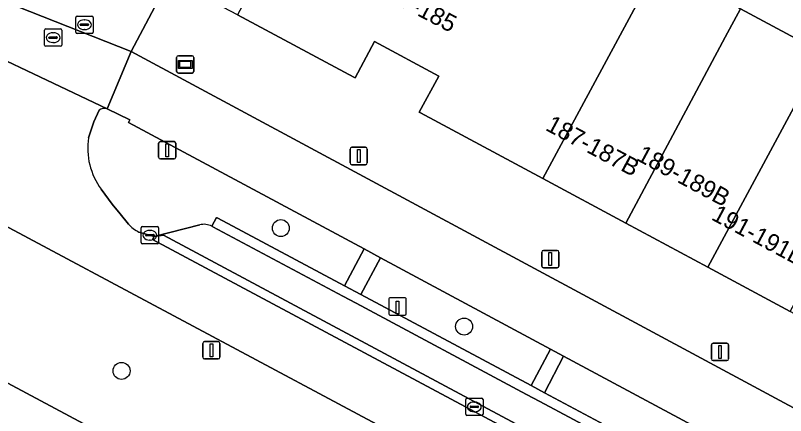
# Model space of a CAD drawing. Extents: x 159489 to 160304, y 383825 to 384531.
# Drawn here: x 159724.49 to 159768.87, y 384033.3 to 384056.37 of the extents above; entities that cross this region are included whole.
import ezdxf

# ---------------------------------------------------------------- set-up
doc = ezdxf.new("R2010")
doc.units = 0
for name, color, linetype in [('IMGEO_Berm_groen', 7, 'Continuous'), ('IMGEO_Boom', 7, 'Continuous'), ('IMGEO_Erf', 7, 'Continuous'), ('IMGEO_Fietspad_gesloten', 7, 'Continuous'), ('IMGEO_Informatiebord', 7, 'Continuous'), ('IMGEO_Kolk', 7, 'Continuous'), ('IMGEO_Laadpaal', 7, 'Continuous'), ('IMGEO_Lichtmast', 7, 'Continuous'), ('IMGEO_OVBaan_gesloten', 7, 'Continuous'), ('IMGEO_Pand', 7, 'Continuous'), ('IMGEO_Pand_nummerreeks', 7, 'Continuous'), ('IMGEO_Parkeervlak_open', 7, 'Continuous'), ('IMGEO_Rijbaan_lokaal_gesloten', 7, 'Continuous'), ('IMGEO_Rijbaan_lokaal_open', 7, 'Continuous'), ('IMGEO_Rioolput', 7, 'Continuous'), ('IMGEO_Verkeersbordpaal', 7, 'Continuous'), ('IMGEO_Voetpad_open', 7, 'Continuous')]:
    doc.layers.add(name, color=color, linetype=linetype)

msp = doc.modelspace()

# ---------------------------------------------------------------- linework, layer by layer
at = {"layer": 'IMGEO_Berm_groen'}
for points in [[(159694.802, 384052.841), (159693.976, 384051.25), (159777.482, 384006.579), (159777.79, 384007.155)], [(159729.317, 384050.915), (159729.003, 384050.242), (159728.705, 384049.324)], [(159731.013, 384050.208), (159731.079, 384050.354), (159729.77, 384050.977)], [(159735.803, 384044.218), (159736.071, 384044.724), (159736.097, 384044.71), (159736.122, 384044.696), (159736.147, 384044.681), (159743.451, 384040.779), (159744.588, 384042.906), (159731.013, 384050.208)], [(159729.441, 384046.354), (159730.06, 384045.499), (159730.518, 384044.924), (159731.001, 384044.339)], [(159794.454, 384006.529), (159791.668, 384008.018), (159791.261, 384007.258), (159782.348, 384012.022), (159782.754, 384012.782), (159722.71, 384044.871)], [(159731.607, 384043.881), (159732.479, 384043.633), (159735.114, 384044.297)]]:
    msp.add_lwpolyline(points, dxfattribs=at)
for points in [[(159745.526, 384042.402), (159744.388, 384040.278), (159754.215, 384035.027), (159755.319, 384037.135)], [(159756.08, 384036.725), (159754.979, 384034.619), (159764.491, 384029.537), (159765.597, 384031.607)]]:
    msp.add_lwpolyline(points, close=True, dxfattribs=at)
for centre, radius, start, end in [((159729.606, 384050.492), 0.513, 71.303, 124.2838), ((159732.611, 384048.716), 3.954, 171.1517, 216.6847), ((159732.536, 384045.74), 2.078, 222.3887, 243.4491), ((159735.358, 384043.377), 0.951, 62.0804, 104.8377)]:
    msp.add_arc(centre, radius, start, end, dxfattribs=at)
at = {"layer": 'IMGEO_Boom'}
for centre in [(159739.784, 384044.112), (159750.343, 384038.433), (159730.609, 384035.874)]:
    msp.add_circle(centre, 0.489, dxfattribs=at)
at = {"layer": 'IMGEO_Erf'}
msp.add_lwpolyline([(159771.882, 384093.775), (159768.398, 384087.297), (159767.715, 384087.664), (159765.263, 384083.106), (159764.285, 384083.651), (159761.719, 384078.881), (159759.162, 384074.125), (159756.604, 384069.369), (159754.192, 384064.841), (159755.61, 384064.079), (159754.307, 384061.657), (159761.088, 384058.01), (159761.728, 384059.201), (159766.267, 384056.759), (159771.029, 384054.198)], dxfattribs=at)
at = {"layer": 'IMGEO_Fietspad_gesloten'}
for points in [[(159722.803, 384054.291), (159729.77, 384050.977), (159731.166, 384054.292), (159724.587, 384056.893)], [(159731.166, 384054.292), (159729.77, 384050.977), (159731.079, 384050.354), (159731.013, 384050.208), (159744.588, 384042.906), (159745.526, 384042.402), (159755.319, 384037.135), (159756.08, 384036.725), (159765.597, 384031.607), (159765.779, 384031.509), (159766.543, 384031.098), (159776.103, 384025.957), (159776.158, 384025.928), (159776.288, 384025.857), (159777.06, 384025.441), (159789.993, 384018.658), (159793.68, 384016.677), (159793.765, 384016.631), (159793.788, 384016.619), (159793.901, 384016.538), (159794.526, 384016.198), (159800.871, 384012.75), (159801.63, 384012.412), (159802.497, 384011.87)], [(159802.594, 384011.19), (159802.971, 384011.597), (159804.049, 384012.761), (159805.225, 384014.454), (159801.988, 384016.22), (159797.098, 384018.803), (159731.166, 384054.292)]]:
    msp.add_lwpolyline(points, dxfattribs=at)
at = {"layer": 'IMGEO_Informatiebord'}
for p, q in [((159733.781, 384053.148), (159733.781, 384053.948)), ((159733.781, 384053.948), (159733.781, 384053.148)), ((159733.881, 384054.048), (159734.671, 384054.048)), ((159734.671, 384054.048), (159733.881, 384054.048)), ((159734.771, 384053.948), (159734.771, 384053.148)), ((159734.771, 384053.148), (159734.771, 384053.948)), ((159734.671, 384053.048), (159733.881, 384053.048)), ((159733.881, 384053.048), (159734.671, 384053.048))]:
    msp.add_line(p, q, dxfattribs=at)
for points in [[(159733.882, 384053.78), (159734.67, 384053.78), (159734.67, 384053.316), (159733.882, 384053.316), (159733.882, 384053.78)], [(159733.947, 384053.715), (159733.947, 384053.381), (159734.605, 384053.381), (159734.605, 384053.715), (159733.947, 384053.715)]]:
    msp.add_lwpolyline(points, dxfattribs=at)
for centre, start, end in [((159733.881, 384053.948), 90, 180), ((159733.881, 384053.948), 90, 180), ((159734.671, 384053.948), 0, 90), ((159734.671, 384053.948), 360, 90), ((159733.881, 384053.148), 180, 270), ((159733.881, 384053.148), 180, 270), ((159734.671, 384053.148), 270, 0), ((159734.671, 384053.148), 270, 0)]:
    msp.add_arc(centre, 0.1, start, end, dxfattribs=at)
at = {"layer": 'IMGEO_Kolk'}
for p, q in [((159731.739, 384043.272), (159731.739, 384044.124)), ((159731.814, 384044.198), (159732.666, 384044.198)), ((159732.74, 384044.124), (159732.74, 384043.272)), ((159731.998, 384043.692), (159731.998, 384043.704)), ((159732.041, 384043.741), (159732.439, 384043.741)), ((159732.227, 384043.978), (159732.252, 384043.978)), ((159732.482, 384043.704), (159732.482, 384043.692)), ((159732.436, 384043.655), (159732.038, 384043.655)), ((159732.25, 384043.418), (159732.225, 384043.418)), ((159732.666, 384043.198), (159731.814, 384043.198)), ((159750.435, 384033.378), (159750.435, 384034.23)), ((159750.51, 384034.304), (159751.362, 384034.304)), ((159750.923, 384034.084), (159750.948, 384034.084)), ((159751.436, 384034.23), (159751.436, 384033.378)), ((159750.694, 384033.798), (159750.694, 384033.81)), ((159751.132, 384033.761), (159750.734, 384033.761)), ((159750.737, 384033.847), (159751.135, 384033.847)), ((159750.946, 384033.524), (159750.921, 384033.524)), ((159751.178, 384033.81), (159751.178, 384033.798)), ((159751.362, 384033.304), (159750.51, 384033.304))]:
    msp.add_line(p, q, dxfattribs=at)
for points in [[(159731.739, 384043.272), (159731.739, 384044.124)], [(159731.814, 384044.198), (159732.666, 384044.198)], [(159732.74, 384044.124), (159732.74, 384043.272)], [(159732.666, 384043.198), (159731.814, 384043.198)], [(159750.435, 384033.378), (159750.435, 384034.23)], [(159750.51, 384034.304), (159751.362, 384034.304)], [(159751.436, 384034.23), (159751.436, 384033.378)], [(159751.362, 384033.304), (159750.51, 384033.304)]]:
    msp.add_lwpolyline(points, dxfattribs=at)
for centre, radius, start, end in [((159731.816, 384044.122), 0.0765, 91.552, 178.448), ((159731.816, 384044.122), 0.0765, 91.552, 178.448), ((159732.664, 384044.122), 0.0765, 1.552, 88.448), ((159732.664, 384044.122), 0.0765, 1.552, 88.448), ((159732.038, 384043.701), 0.0403, 85.8775, 175.7526), ((159732.035, 384043.691), 0.0366, 178.938, 274.7102), ((159732.439, 384043.698), 0.043, 264.8664, 352.4533), ((159732.443, 384043.703), 0.0386, 1.7309, 96.639), ((159731.816, 384043.274), 0.0765, 181.552, 268.448), ((159731.816, 384043.274), 0.0765, 181.552, 268.448), ((159732.664, 384043.274), 0.0765, 271.552, 358.448), ((159732.664, 384043.274), 0.0765, 271.552, 358.448), ((159750.512, 384034.228), 0.0765, 91.552, 178.448), ((159750.512, 384034.228), 0.0765, 91.552, 178.448), ((159751.36, 384034.228), 0.0765, 1.552, 88.448), ((159751.36, 384034.228), 0.0765, 1.552, 88.448), ((159750.734, 384033.807), 0.0403, 85.8775, 175.7526), ((159750.731, 384033.797), 0.0366, 178.938, 274.7102), ((159751.135, 384033.804), 0.043, 264.8664, 352.4533), ((159751.139, 384033.809), 0.0386, 1.7309, 96.639), ((159750.512, 384033.38), 0.0765, 181.552, 268.448), ((159750.512, 384033.38), 0.0765, 181.552, 268.448), ((159751.36, 384033.38), 0.0765, 271.552, 358.448), ((159751.36, 384033.38), 0.0765, 271.552, 358.448)]:
    msp.add_arc(centre, radius, start, end, dxfattribs=at)
for centre, major_axis, ratio, start_param, end_param in [((159732.226, 384043.698), (-0.387, 0.002), 0.722429, 4.712389, 7.853982), ((159732.251, 384043.698), (-0.39, 0.002), 0.717154, 1.570796, 4.712389), ((159750.922, 384033.804), (-0.387, 0.002), 0.722429, 4.712389, 7.853982), ((159750.947, 384033.804), (-0.39, 0.002), 0.717154, 1.570796, 4.712389)]:
    msp.add_ellipse(centre, major_axis=major_axis, ratio=ratio, start_param=start_param, end_param=end_param, dxfattribs=at)
at = {"layer": 'IMGEO_Laadpaal'}
for p, q in [((159746.011, 384040.009), (159746.011, 384039.168)), ((159746.011, 384040.009), (159746.011, 384039.168)), ((159746.927, 384040.093), (159746.086, 384040.093)), ((159746.927, 384040.093), (159746.086, 384040.093)), ((159747.011, 384039.177), (159747.011, 384040.018)), ((159747.011, 384039.177), (159747.011, 384040.018)), ((159746.095, 384039.093), (159746.936, 384039.093)), ((159746.095, 384039.093), (159746.936, 384039.093))]:
    msp.add_line(p, q, dxfattribs=at)
msp.add_lwpolyline([(159746.426, 384039.906), (159746.586, 384039.906), (159746.586, 384039.173), (159746.426, 384039.173), (159746.426, 384039.906)], dxfattribs=at)
for centre, start, end in [((159746.089, 384040.015), 92.4484, 184.2845), ((159746.089, 384040.015), 92.4484, 184.2845), ((159746.933, 384040.015), 2.4484, 94.2845), ((159746.933, 384040.015), 2.4484, 94.2845), ((159746.089, 384039.171), 182.4484, 274.2845), ((159746.089, 384039.171), 182.4484, 274.2845), ((159746.933, 384039.171), 272.4484, 4.2845), ((159746.933, 384039.171), 272.4484, 4.2845)]:
    msp.add_arc(centre, 0.0779, start, end, dxfattribs=at)
at = {"layer": 'IMGEO_Lichtmast'}
for p, q in [((159743.778, 384047.867), (159743.778, 384048.667)), ((159743.778, 384048.667), (159743.778, 384047.867)), ((159743.878, 384048.767), (159744.668, 384048.767)), ((159744.668, 384048.767), (159743.878, 384048.767)), ((159744.768, 384048.667), (159744.768, 384047.867)), ((159744.768, 384047.867), (159744.768, 384048.667)), ((159744.668, 384047.767), (159743.878, 384047.767)), ((159743.878, 384047.767), (159744.668, 384047.767)), ((159754.915, 384042.823), (159755.705, 384042.823)), ((159755.705, 384042.823), (159754.915, 384042.823)), ((159754.815, 384041.923), (159754.815, 384042.723)), ((159754.815, 384042.723), (159754.815, 384041.923)), ((159755.805, 384042.723), (159755.805, 384041.923)), ((159755.805, 384041.923), (159755.805, 384042.723)), ((159755.705, 384041.823), (159754.915, 384041.823)), ((159754.915, 384041.823), (159755.705, 384041.823)), ((159735.287, 384036.664), (159735.287, 384037.464)), ((159735.287, 384037.464), (159735.287, 384036.664)), ((159735.387, 384037.564), (159736.177, 384037.564)), ((159736.177, 384037.564), (159735.387, 384037.564)), ((159736.277, 384037.464), (159736.277, 384036.664)), ((159736.277, 384036.664), (159736.277, 384037.464)), ((159764.695, 384037.473), (159765.485, 384037.473)), ((159765.485, 384037.473), (159764.695, 384037.473)), ((159764.595, 384036.573), (159764.595, 384037.373)), ((159764.595, 384037.373), (159764.595, 384036.573)), ((159765.585, 384037.373), (159765.585, 384036.573)), ((159765.585, 384036.573), (159765.585, 384037.373)), ((159736.177, 384036.564), (159735.387, 384036.564)), ((159735.387, 384036.564), (159736.177, 384036.564)), ((159765.485, 384036.473), (159764.695, 384036.473)), ((159764.695, 384036.473), (159765.485, 384036.473))]:
    msp.add_line(p, q, dxfattribs=at)
for points in [[(159744.198, 384048.642), (159744.348, 384048.642), (159744.348, 384047.892), (159744.198, 384047.892), (159744.198, 384048.642)], [(159755.235, 384042.698), (159755.385, 384042.698), (159755.385, 384041.948), (159755.235, 384041.948), (159755.235, 384042.698)], [(159735.707, 384037.439), (159735.857, 384037.439), (159735.857, 384036.689), (159735.707, 384036.689), (159735.707, 384037.439)], [(159765.015, 384037.348), (159765.165, 384037.348), (159765.165, 384036.598), (159765.015, 384036.598), (159765.015, 384037.348)]]:
    msp.add_lwpolyline(points, dxfattribs=at)
for centre, start, end in [((159743.878, 384048.667), 90, 180), ((159743.878, 384048.667), 90, 180), ((159744.668, 384048.667), 0, 90), ((159744.668, 384048.667), 360, 90), ((159743.878, 384047.867), 180, 270), ((159743.878, 384047.867), 180, 270), ((159744.668, 384047.867), 270, 0), ((159744.668, 384047.867), 270, 0), ((159754.915, 384042.723), 90, 180), ((159754.915, 384042.723), 90, 180), ((159755.705, 384042.723), 0, 90), ((159755.705, 384042.723), 360, 90), ((159754.915, 384041.923), 180, 270), ((159754.915, 384041.923), 180, 270), ((159755.705, 384041.923), 270, 0), ((159755.705, 384041.923), 270, 0), ((159735.387, 384037.464), 90, 180), ((159735.387, 384037.464), 90, 180), ((159736.177, 384037.464), 0, 90), ((159736.177, 384037.464), 360, 90), ((159764.695, 384037.373), 90, 180), ((159764.695, 384037.373), 90, 180), ((159765.485, 384037.373), 0, 90), ((159765.485, 384037.373), 360, 90), ((159735.387, 384036.664), 180, 270), ((159735.387, 384036.664), 180, 270), ((159736.177, 384036.664), 270, 0), ((159736.177, 384036.664), 270, 0), ((159764.695, 384036.573), 180, 270), ((159764.695, 384036.573), 180, 270), ((159765.485, 384036.573), 270, 0), ((159765.485, 384036.573), 270, 0)]:
    msp.add_arc(centre, 0.1, start, end, dxfattribs=at)
at = {"layer": 'IMGEO_OVBaan_gesloten'}
msp.add_lwpolyline([(159777.995, 384006.304), (159777.482, 384006.579), (159693.976, 384051.25), (159656.977, 384071.043), (159654.816, 384072.267)], dxfattribs=at)
at = {"layer": 'IMGEO_Pand'}
for points in [[(159745.606, 384069.324), (159744.543, 384069.861), (159737.293, 384056.412), (159744, 384052.814), (159744.059, 384052.782), (159745.177, 384054.872), (159748.885, 384052.879), (159747.763, 384050.791), (159747.838, 384050.751), (159754.877, 384046.966), (159760.634, 384057.677), (159760.847, 384057.561), (159761.088, 384058.01), (159754.307, 384061.657), (159755.61, 384064.079), (159754.192, 384064.841), (159754.136, 384064.736)], [(159765.389, 384055.118), (159766.267, 384056.759), (159761.728, 384059.201), (159761.088, 384058.01), (159760.847, 384057.561), (159760.634, 384057.677), (159754.877, 384046.966), (159759.654, 384044.398)], [(159770.147, 384052.559), (159771.029, 384054.198), (159766.267, 384056.759), (159765.389, 384055.118), (159759.654, 384044.398), (159764.388, 384041.852)], [(159774.902, 384050.001), (159775.785, 384051.64), (159771.029, 384054.198), (159770.147, 384052.559), (159764.388, 384041.852), (159769.137, 384039.299)]]:
    msp.add_lwpolyline(points, close=True, dxfattribs=at)
at = {"layer": 'IMGEO_Parkeervlak_open'}
for points in [[(159735.114, 384044.297), (159732.479, 384043.633), (159733.023, 384043.708), (159783.959, 384016.413), (159783.95, 384016.527), (159783.314, 384018.492)], [(159754.714, 384034.111), (159753.949, 384034.52), (159744.117, 384039.773), (159743.356, 384040.18), (159735.862, 384044.184)], [(159782.841, 384019.083), (159782.699, 384019.159), (159775.691, 384022.903), (159774.939, 384023.305), (159765.175, 384028.522), (159764.408, 384028.932), (159754.714, 384034.111)]]:
    msp.add_lwpolyline(points, dxfattribs=at)
for centre, radius, start, end in [((159735.358, 384043.377), 0.951, 62.0804, 104.8377), ((159735.573, 384043.752), 0.52, 56.2914, 63.8014)]:
    msp.add_arc(centre, radius, start, end, dxfattribs=at)
at = {"layer": 'IMGEO_Rijbaan_lokaal_gesloten'}
for points in [[(159785.842, 384170.895), (159785.06, 384169.44), (159732.135, 384070.941), (159724.587, 384056.893), (159731.166, 384054.292), (159733.379, 384058.49), (159735.26, 384062.057), (159733.476, 384062.998), (159733.684, 384063.394), (159756.933, 384106.574), (159758.71, 384105.618), (159759.915, 384107.857), (159758.589, 384108.571)], [(159729.77, 384050.977), (159722.803, 384054.291)], [(159728.705, 384049.324), (159729.003, 384050.242), (159729.317, 384050.915)], [(159731.001, 384044.339), (159730.518, 384044.924), (159730.06, 384045.499), (159729.441, 384046.354)], [(159722.71, 384044.871), (159782.754, 384012.782), (159791.668, 384008.018), (159794.454, 384006.529)], [(159785.598, 384015.039), (159784.967, 384015.376), (159784.85, 384015.386), (159732.397, 384043.459), (159732.479, 384043.633), (159731.607, 384043.881)]]:
    msp.add_lwpolyline(points, dxfattribs=at)
for centre, radius, start, end in [((159729.606, 384050.492), 0.513, 71.303, 124.2838), ((159732.611, 384048.716), 3.954, 171.1517, 216.6847), ((159732.536, 384045.74), 2.078, 222.3887, 243.4491)]:
    msp.add_arc(centre, radius, start, end, dxfattribs=at)
at = {"layer": 'IMGEO_Rijbaan_lokaal_open'}
for points in [[(159733.023, 384043.708), (159732.479, 384043.633), (159732.397, 384043.459), (159784.85, 384015.386), (159784.967, 384015.376)], [(159783.95, 384016.527), (159783.959, 384016.413), (159733.023, 384043.708)]]:
    msp.add_lwpolyline(points, dxfattribs=at)
at = {"layer": 'IMGEO_Rioolput'}
for p, q in [((159727.968, 384055.409), (159727.968, 384056.261)), ((159728.043, 384056.335), (159728.895, 384056.335)), ((159728.456, 384056.115), (159728.481, 384056.115)), ((159728.969, 384056.261), (159728.969, 384055.409)), ((159728.227, 384055.829), (159728.227, 384055.841)), ((159728.665, 384055.792), (159728.267, 384055.792)), ((159728.27, 384055.878), (159728.668, 384055.878)), ((159728.711, 384055.841), (159728.711, 384055.829)), ((159726.163, 384054.665), (159726.163, 384055.517)), ((159726.238, 384055.591), (159727.09, 384055.591)), ((159726.651, 384055.371), (159726.676, 384055.371)), ((159727.164, 384055.517), (159727.164, 384054.665)), ((159728.895, 384055.335), (159728.043, 384055.335)), ((159728.479, 384055.555), (159728.454, 384055.555)), ((159726.422, 384055.085), (159726.422, 384055.097)), ((159726.86, 384055.048), (159726.462, 384055.048)), ((159726.465, 384055.134), (159726.863, 384055.134)), ((159726.674, 384054.811), (159726.649, 384054.811)), ((159726.906, 384055.097), (159726.906, 384055.085)), ((159727.09, 384054.591), (159726.238, 384054.591))]:
    msp.add_line(p, q, dxfattribs=at)
for points in [[(159727.968, 384055.409), (159727.968, 384056.261)], [(159728.043, 384056.335), (159728.895, 384056.335)], [(159728.969, 384056.261), (159728.969, 384055.409)], [(159726.163, 384054.665), (159726.163, 384055.517)], [(159726.238, 384055.591), (159727.09, 384055.591)], [(159727.164, 384055.517), (159727.164, 384054.665)], [(159728.895, 384055.335), (159728.043, 384055.335)], [(159727.09, 384054.591), (159726.238, 384054.591)]]:
    msp.add_lwpolyline(points, dxfattribs=at)
for centre, radius, start, end in [((159728.045, 384056.259), 0.0765, 91.552, 178.448), ((159728.045, 384056.259), 0.0765, 91.552, 178.448), ((159728.893, 384056.259), 0.0765, 1.552, 88.448), ((159728.893, 384056.259), 0.0765, 1.552, 88.448), ((159728.267, 384055.838), 0.0403, 85.8775, 175.7526), ((159728.264, 384055.828), 0.0366, 178.938, 274.7102), ((159728.668, 384055.835), 0.043, 264.8664, 352.4533), ((159728.672, 384055.84), 0.0386, 1.7309, 96.639), ((159726.24, 384055.515), 0.0765, 91.552, 178.448), ((159726.24, 384055.515), 0.0765, 91.552, 178.448), ((159727.088, 384055.515), 0.0765, 1.552, 88.448), ((159727.088, 384055.515), 0.0765, 1.552, 88.448), ((159728.045, 384055.411), 0.0765, 181.552, 268.448), ((159728.045, 384055.411), 0.0765, 181.552, 268.448), ((159728.893, 384055.411), 0.0765, 271.552, 358.448), ((159728.893, 384055.411), 0.0765, 271.552, 358.448), ((159726.462, 384055.094), 0.0403, 85.8775, 175.7526), ((159726.459, 384055.084), 0.0366, 178.938, 274.7102), ((159726.863, 384055.091), 0.043, 264.8664, 352.4533), ((159726.867, 384055.096), 0.0386, 1.7309, 96.639), ((159726.24, 384054.667), 0.0765, 181.552, 268.448), ((159726.24, 384054.667), 0.0765, 181.552, 268.448), ((159727.088, 384054.667), 0.0765, 271.552, 358.448), ((159727.088, 384054.667), 0.0765, 271.552, 358.448)]:
    msp.add_arc(centre, radius, start, end, dxfattribs=at)
for centre, major_axis, ratio, start_param, end_param in [((159728.455, 384055.835), (-0.387, 0.002), 0.722429, 4.712389, 7.853982), ((159728.48, 384055.835), (-0.39, 0.002), 0.717154, 1.570796, 4.712389), ((159726.65, 384055.091), (-0.387, 0.002), 0.722429, 4.712389, 7.853982), ((159726.675, 384055.091), (-0.39, 0.002), 0.717154, 1.570796, 4.712389)]:
    msp.add_ellipse(centre, major_axis=major_axis, ratio=ratio, start_param=start_param, end_param=end_param, dxfattribs=at)
at = {"layer": 'IMGEO_Verkeersbordpaal'}
for p, q in [((159732.744, 384048.199), (159732.744, 384048.999)), ((159732.744, 384048.999), (159732.744, 384048.199)), ((159732.844, 384049.099), (159733.634, 384049.099)), ((159733.634, 384049.099), (159732.844, 384049.099)), ((159733.734, 384048.999), (159733.734, 384048.199)), ((159733.734, 384048.199), (159733.734, 384048.999)), ((159733.634, 384048.099), (159732.844, 384048.099)), ((159732.844, 384048.099), (159733.634, 384048.099))]:
    msp.add_line(p, q, dxfattribs=at)
msp.add_lwpolyline([(159733.164, 384048.974), (159733.314, 384048.974), (159733.314, 384048.224), (159733.164, 384048.224), (159733.164, 384048.974)], dxfattribs=at)
for centre, start, end in [((159732.844, 384048.999), 90, 180), ((159732.844, 384048.999), 90, 180), ((159733.634, 384048.999), 0, 90), ((159733.634, 384048.999), 360, 90), ((159732.844, 384048.199), 180, 270), ((159732.844, 384048.199), 180, 270), ((159733.634, 384048.199), 270, 0), ((159733.634, 384048.199), 270, 0)]:
    msp.add_arc(centre, 0.1, start, end, dxfattribs=at)
at = {"layer": 'IMGEO_Voetpad_open'}
for points in [[(159748.885, 384052.879), (159745.177, 384054.872), (159744.059, 384052.782), (159744, 384052.814), (159737.293, 384056.412), (159733.379, 384058.49), (159731.166, 384054.292), (159797.098, 384018.803), (159799.393, 384023.037), (159796.313, 384024.693), (159790.874, 384027.608), (159790.367, 384028.077), (159785.732, 384030.559), (159785.645, 384030.424), (159778.666, 384034.176), (159773.904, 384036.736), (159769.137, 384039.299), (159764.388, 384041.852), (159759.654, 384044.398), (159754.877, 384046.966), (159747.838, 384050.751), (159747.763, 384050.791)], [(159745.526, 384042.402), (159744.588, 384042.906), (159743.451, 384040.779), (159744.388, 384040.278)], [(159756.08, 384036.725), (159755.319, 384037.135), (159754.215, 384035.027), (159754.979, 384034.619)]]:
    msp.add_lwpolyline(points, close=True, dxfattribs=at)
for points in [[(159754.979, 384034.619), (159754.215, 384035.027), (159744.388, 384040.278), (159743.451, 384040.779), (159736.147, 384044.681), (159736.122, 384044.696), (159736.097, 384044.71), (159736.071, 384044.724), (159735.803, 384044.218)], [(159735.862, 384044.184), (159743.356, 384040.18), (159744.117, 384039.773), (159753.949, 384034.52), (159754.714, 384034.111), (159764.408, 384028.932), (159765.175, 384028.522), (159774.939, 384023.305), (159775.691, 384022.903), (159782.699, 384019.159), (159782.969, 384019.664), (159775.963, 384023.407), (159775.207, 384023.811), (159775.067, 384023.886), (159775.012, 384023.915), (159765.444, 384029.028), (159764.677, 384029.438), (159764.491, 384029.537), (159754.979, 384034.619)]]:
    msp.add_lwpolyline(points, dxfattribs=at)
msp.add_arc((159735.573, 384043.752), 0.52, 56.2914, 63.8014, dxfattribs=at)

# ---------------------------------------------------------------- texts
at = {"layer": 'IMGEO_Pand_nummerreeks'}
for s, rotation, p in [('167-185', 332.3598, (159745.224, 384057.636)), ('187-187B', 331.8391, (159754.979, 384049.785)), ('189-189B', 331.6902, (159760.209, 384048.062)), ('191-191B', 331.7818, (159764.533, 384044.627))]:
    msp.add_text(s, height=1, rotation=rotation, dxfattribs=at).set_placement(p)

doc.saveas('drawing.dxf')
